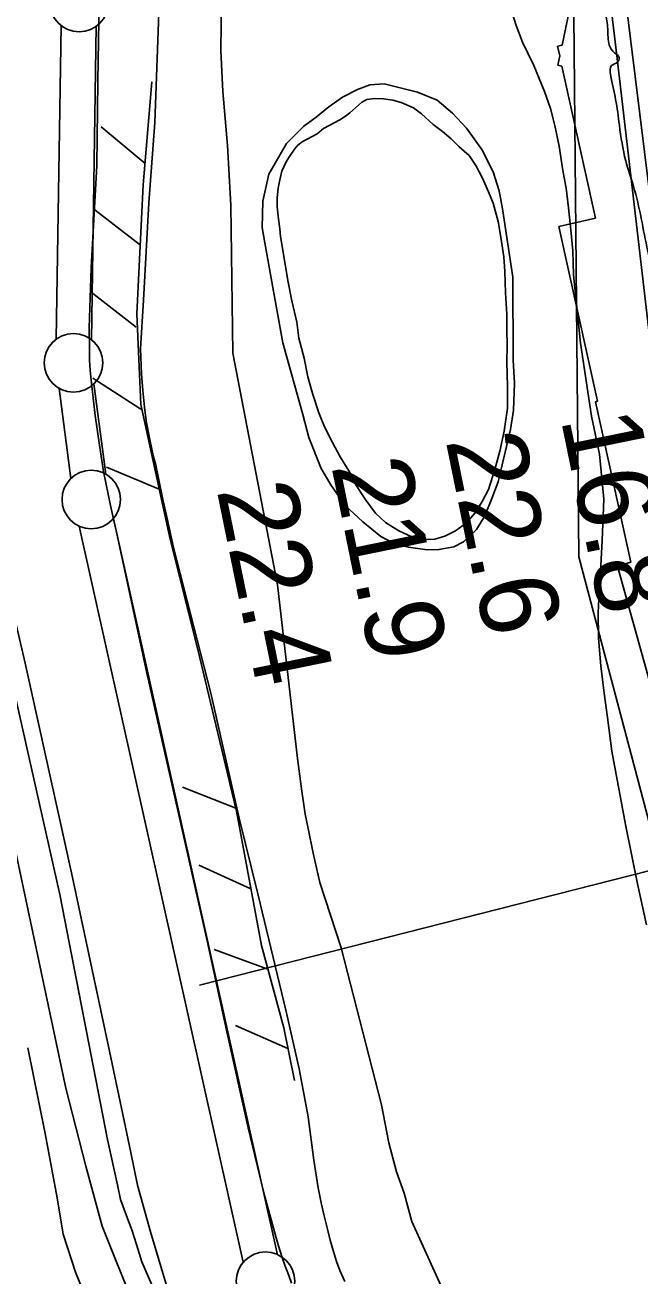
# Model space of a CAD drawing. Extents: x 3424494 to 3462436, y 522220 to 547718.
# Drawn here: x 3438050 to 3438575, y 543668 to 544736 of the extents above; entities that cross this region are included whole.
import ezdxf

# ---------------------------------------------------------------- set-up
doc = ezdxf.new("R2010")
doc.units = 0
for name, color, linetype in [('V-FLOD-BASE', 7, 'Continuous'), ('V-LEVE-TOET', 7, 'Continuous'), ('V-RIVR-EDGE', 7, 'Continuous'), ('V-RIVR-RANG', 7, 'Continuous'), ('V-ROAD-CNTR', 7, 'Continuous'), ('V-RRAP-FSHR', 7, 'Continuous'), ('V-RRAP-RVMT', 7, 'Continuous'), ('V-SITE-VEGE', 7, 'Continuous'), ('V-SURV-LINE', 7, 'Continuous'), ('V-TOPO-DPTH', 7, 'Continuous'), ('V-TOPO-MINR', 7, 'Continuous'), ('V-TOPO-SHOR', 7, 'Continuous')]:
    doc.layers.add(name, color=color, linetype=linetype)

msp = doc.modelspace()

# ---------------------------------------------------------------- linework, layer by layer
at = {"layer": 'V-FLOD-BASE'}
msp.add_lwpolyline([(3438113.5, 544757.3), (3438112.3, 544687.9), (3438111.3, 544616.3), (3438106.5, 544528.9), (3438105, 544477.6), (3438105.1, 544459.8), (3438105.1, 544450.1), (3438105.8, 544441.5), (3438106.4, 544435.6), (3438107.1, 544427.9), (3438109.9, 544402.9), (3438113.6, 544377.6), (3438117.1, 544355.1), (3438123, 544326.1), (3438129.7, 544296.8), (3438153.8, 544184.5), (3438185.2, 544045.4), (3438205.6, 543954.4), (3438222.2, 543878.3), (3438240.8, 543794.9), (3438254.1, 543739.3), (3438264.1, 543702.9), (3438266.6, 543694.3), (3438268.1, 543689.7), (3438270.1, 543683.4), (3438272.4, 543676.9), (3438274, 543672.6), (3438275.5, 543668.8), (3438277.8, 543662.4)], dxfattribs=at)
at = {"layer": 'V-LEVE-TOET'}
for points in [[(3438028.1, 544800.2), (3438027, 544704), (3438012.2, 544549), (3438005.9, 544448), (3438007.1, 544424), (3438010.5, 544382.3), (3438018.3, 544337.7), (3438027, 544290.4), (3438050.2, 544191.5), (3438089.7, 544012.5), (3438122.3, 543860.4), (3438140.5, 543773.8), (3438146.3, 543746), (3438157.2, 543706.2), (3438172.9, 543653.8), (3438191.3, 543608.8), (3438215.1, 543564.4), (3438236.7, 543528.4), (3438271.5, 543473.1)], [(3438164.4, 544746.4), (3438160.9, 544652.8), (3438155.8, 544584.3), (3438151.4, 544501.3), (3438148.6, 544459.7), (3438149.5, 544438), (3438150.7, 544424.2), (3438152, 544409.9), (3438153.6, 544398.2), (3438156.7, 544382.3), (3438159.6, 544368.8), (3438161.8, 544360.4), (3438167.5, 544332.7)], [(3438167.5, 544332.7), (3438171.6, 544314.9), (3438176.8, 544290.1), (3438208.9, 544165.8), (3438233, 544059.1), (3438249, 543994.5), (3438273.2, 543894.3), (3438284.1, 543845.2), (3438291.8, 543804.2), (3438296.8, 543767.3), (3438300.4, 543743.8), (3438302.9, 543730.8), (3438305.3, 543720.8), (3438308.3, 543708.4), (3438310.8, 543698.9), (3438313.5, 543689.3), (3438316.1, 543680.7), (3438319, 543673.1), (3438323.3, 543663.8)]]:
    msp.add_lwpolyline(points, dxfattribs=at)
at = {"layer": 'V-RIVR-EDGE'}
msp.add_spline([(3438393.4, 545837.6), (3438393.6, 545836.9), (3438395.1, 545831.4), (3438401.6, 545826.6), (3438403.8, 545821.1), (3438403.8, 545813.5), (3438405.2, 545801.8), (3438408.5, 545786.4), (3438409.2, 545778), (3438409.2, 545769.9), (3438409.5, 545757.1), (3438410.9, 545744.7), (3438420.3, 545688.8), (3438423.5, 545652.9), (3438428.9, 545606.1), (3438430.6, 545570.3), (3438432.4, 545549.1), (3438435.9, 545504.1), (3438439.2, 545485.5), (3438445, 545463.9), (3438449.3, 545451.8), (3438457.7, 545444.1), (3438458.1, 545439), (3438458.8, 545433.1), (3438463.5, 545430.2), (3438470.8, 545426.9), (3438472.6, 545421.4), (3438472.2, 545413), (3438471.1, 545394.7), (3438468.1, 545380.8), (3438467.8, 545375.4), (3438465.5, 545364.4), (3438464.8, 545351.2), (3438465.9, 545339.9), (3438471.7, 545328.9), (3438480.7, 545301.9), (3438480.7, 545287.2), (3438482.1, 545273.7), (3438487.2, 545258), (3438494.1, 545247), (3438498.9, 545239.3), (3438502.9, 545227.2), (3438508.3, 545196.5), (3438511.1, 545174.2), (3438523.4, 545123), (3438525.6, 545104.7), (3438525.6, 545098.1), (3438527.7, 545082.4), (3438531, 545064.9), (3438530.9, 545051.3), (3438530.5, 545038.9), (3438527.6, 545030.9), (3438526.8, 545021), (3438528.6, 545002.7), (3438527.5, 544975.7), (3438526.3, 544955.6), (3438524.8, 544938.8), (3438527, 544931.8), (3438537.9, 544918.3), (3438543.7, 544908.4), (3438545.5, 544899.2), (3438545.5, 544889.7), (3438542.6, 544875.1), (3438542.2, 544862.7), (3438543.6, 544857.2), (3438543.6, 544855), (3438540.7, 544850.6), (3438539.2, 544841.1), (3438540.3, 544827.2), (3438541.7, 544817.7), (3438545, 544805.3), (3438544.9, 544790.3), (3438543.4, 544767.3), (3438545.9, 544746.4), (3438547.7, 544732.9), (3438549.1, 544719), (3438553.5, 544712.4), (3438557.5, 544708.4), (3438557.1, 544706.2), (3438556, 544704.4), (3438550.9, 544701.5), (3438550.2, 544693.8), (3438554.5, 544672.6), (3438557.7, 544650.6), (3438563.1, 544620.3), (3438569.7, 544598.7), (3438582, 544543.1), (3438585.2, 544523), (3438584.8, 544506.5), (3438588.4, 544491.2), (3438594.9, 544472.5), (3438598.6, 544459), (3438598.5, 544439.6), (3438598.5, 544425), (3438598.1, 544411.8), (3438598.1, 544405.6), (3438599.5, 544397.6), (3438604.2, 544381.1), (3438610.4, 544357), (3438613.3, 544341.6), (3438619.1, 544333.2), (3438624.9, 544321.1), (3438628.1, 544301.7), (3438628.8, 544279.4), (3438635, 544260), (3438635, 544251.3), (3438637.8, 544233.3), (3438638.5, 544216.2), (3438645.1, 544204.1), (3438650.9, 544193.1), (3438650.9, 544182.1), (3438651.6, 544159.1), (3438651.5, 544153.2), (3438653, 544137.5), (3438657.3, 544124), (3438667.1, 544092.9), (3438672.9, 544069.5), (3438679.8, 544048.6), (3438680.5, 544035.5), (3438681.9, 544024.5), (3438680.4, 544017.2), (3438685.5, 544000.7), (3438686.9, 543981.7), (3438692.7, 543957.6), (3438693.8, 543933.1), (3438694.1, 543918.1), (3438698.1, 543900.5), (3438698.4, 543889.9), (3438698.4, 543885.6), (3438701, 543885.2), (3438708.6, 543887.7), (3438712.6, 543882.6), (3438718.5, 543864.7), (3438733.3, 543818.2), (3438741.3, 543793.7), (3438746.7, 543767.4), (3438754, 543734.1), (3438762.3, 543699), (3438771, 543671.5), (3438780, 543642.6), (3438782.9, 543630.9), (3438781.8, 543630.9), (3438771.2, 543630.2), (3438766.9, 543628.8), (3438765.7, 543622.6), (3438771.2, 543615.2), (3438777, 543602.4), (3438775.2, 543590), (3438778.8, 543582.3), (3438781.7, 543581.2), (3438785.7, 543582.3), (3438793.1, 543586.3), (3438797.8, 543584.8), (3438800.4, 543578.2), (3438805.8, 543546.1), (3438811.9, 543525.9), (3438819.5, 543497), (3438822.8, 543490.1), (3438824.6, 543485), (3438830.1, 543471.4), (3438839.9, 543450.9), (3438843.9, 543441.8), (3438850.4, 543423.9), (3438851.9, 543417.3), (3438850.8, 543408.1), (3438850.4, 543400.8), (3438855.1, 543386.2), (3438860.2, 543372.3), (3438866.7, 543366.1), (3438867.8, 543356.5), (3438867.8, 543347.8), (3438868.9, 543341.2), (3438880.5, 543326.9), (3438889.6, 543313), (3438898.7, 543294), (3438902, 543280.1), (3438906, 543265.1), (3438917.2, 543229.6), (3438923, 543209.5), (3438927.7, 543203.6), (3438932.8, 543185.7), (3438937.1, 543160.8), (3438942.6, 543134.8), (3438946.9, 543117.6), (3438946.9, 543110.3), (3438946.5, 543102.7), (3438951.2, 543091.7), (3438960.7, 543082.5), (3438961.4, 543076.7), (3438965.4, 543063.9), (3438966.5, 543053.3), (3438963.9, 543047.4), (3438962.1, 543042.7), (3438965.3, 543026.9), (3438970.4, 543005.4), (3438977.3, 542983.8), (3438982.7, 542973.9), (3438991.8, 542954.9), (3439000.9, 542934), (3439008.6, 542918.6), (3439023.8, 542895.6), (3439028.2, 542883.1), (3439037, 542873.2), (3439040.9, 542860.8), (3439048.2, 542843.6), (3439058.8, 542827.9), (3439070.4, 542802.6), (3439079.5, 542782.8), (3439082.4, 542763.5), (3439082.7, 542749.2), (3439081.6, 542735.3), (3439079.3, 542717.4), (3439079, 542710.5), (3439082.9, 542696.9), (3439086.2, 542687.8), (3439090.6, 542683.8), (3439099.4, 542684.1), (3439102.3, 542680.1), (3439104.1, 542676), (3439104.1, 542668.4), (3439104, 542657.4), (3439105.5, 542647.5), (3439106.2, 542642), (3439115.3, 542621.2), (3439129.1, 542598.9), (3439132.4, 542599.6), (3439141.5, 542584.2), (3439147.3, 542566.6), (3439154.6, 542546.9), (3439164, 542527.5), (3439169.8, 542510.7), (3439173.5, 542500), (3439177.5, 542490.9), (3439190.6, 542472.2), (3439206.2, 542447.3), (3439209.1, 542433.1), (3439211.3, 542426.8), (3439222.3, 542418.4), (3439225.9, 542411.8), (3439227.3, 542401.2), (3439229.9, 542396.1), (3439237.5, 542388), (3439240.4, 542378.9), (3439243, 542371.2), (3439252.8, 542351.1), (3439262.6, 542326.2), (3439271.7, 542310.8), (3439276.4, 542291.8), (3439280.4, 542275.3), (3439282.6, 542264.7), (3439280.4, 542261.1), (3439278.2, 542259.3), (3439283.2, 542243.9), (3439285.4, 542231.8), (3439293.1, 542221.2), (3439297.1, 542211.7), (3439308.3, 542194.5), (3439310.9, 542190.4), (3439316.4, 542190.1), (3439317.5, 542186), (3439322.9, 542161.5), (3439326.9, 542146.2), (3439328.7, 542133.4), (3439327.9, 542118.8), (3439331.1, 542099.7), (3439347.1, 542053.3), (3439351.8, 542035.4), (3439360.5, 542018.9), (3439371.1, 542000.6), (3439381.3, 541982.6), (3439394.1, 541973.1), (3439397.7, 541966.9), (3439399.9, 541955.5), (3439406.1, 541943.5), (3439414.8, 541930.7), (3439422.8, 541920.8), (3439437.8, 541904.6), (3439450.5, 541882.3), (3439460.7, 541852.7), (3439464.7, 541843.9), (3439468.3, 541833.3), (3439481.8, 541815.3), (3439490.1, 541800.7), (3439498.5, 541788.6), (3439505.1, 541778.4), (3439505.4, 541771.4), (3439505.7, 541754.6), (3439506.8, 541747.7), (3439515.2, 541733.7), (3439522.8, 541717.3), (3439531.2, 541708.8), (3439533.8, 541701.2), (3439533.7, 541689.8), (3439534.1, 541670.5), (3439534, 541662), (3439535.5, 541656.6), (3439543.5, 541645.2), (3439555.9, 541625.8), (3439565.7, 541607.5), (3439574, 541583.7), (3439582.8, 541562.5), (3439587.5, 541546.4), (3439591.9, 541542.7), (3439598.8, 541540.2), (3439601.3, 541536.5), (3439607.5, 541524.8), (3439631.5, 541476.8), (3439645.7, 541442.1), (3439652.6, 541429.6), (3439663.2, 541408), (3439674.8, 541397.8), (3439682.8, 541381.3)], degree=3, dxfattribs=at)
at = {"layer": 'V-RIVR-RANG'}
msp.add_line((3438199.1, 543916.7), (3439265.3, 544187.5), dxfattribs=at)
at = {"layer": 'V-ROAD-CNTR'}
msp.add_lwpolyline([(3437857.8, 545838.4), (3437892.6, 545547.7), (3437938.2, 545159.2), (3437964.7, 544952.5), (3437976, 544792.9), (3437969.2, 544630.2), (3437963.9, 544485.3), (3437979.7, 544339.6), (3438022.4, 544122.5), (3438085.1, 543828.8), (3438101.9, 543762.2), (3438116.1, 543710.9), (3438143.5, 543642.1), (3438173.7, 543575.3), (3438251, 543447.6), (3438348.6, 543287), (3438420.9, 543170.8), (3438482.6, 543068.5), (3438531.5, 542958.1)], dxfattribs=at)
at = {"layer": 'V-RRAP-FSHR'}
for p, q in [((3438152.6, 544618), (3438115.1, 544649.2)), ((3438148.6, 544548.1), (3438110, 544578)), ((3438145.1, 544478.2), (3438106.5, 544508.1)), ((3438149.1, 544408.2), (3438107.9, 544434.6)), ((3438164.7, 544339.9), (3438119.7, 544358.7)), ((3438230, 544067.7), (3438184.6, 544085.6)), ((3438243, 543998.9), (3438198.5, 544019.1)), ((3438257.4, 543930.4), (3438211.5, 543947)), ((3438274.6, 543862.6), (3438229.8, 543882.1))]:
    msp.add_line(p, q, dxfattribs=at)
for points in [[(3438158.5, 544687.7), (3438151.1, 544599.8), (3438145.7, 544489.6), (3438148.9, 544412.2), (3438173.5, 544299.9), (3438199, 544197.2), (3438230.6, 544065.1), (3438252, 543950.6), (3438271, 543880.3), (3438280.1, 543835.2)], [(3438158.5, 544687.7), (3438151.1, 544599.8), (3438145.7, 544489.6), (3438148.9, 544412.2), (3438163.7, 544344.8)], [(3438225, 544088.7), (3438230.6, 544065.1), (3438252, 543950.6), (3438271, 543880.3), (3438280.1, 543835.2)]]:
    msp.add_lwpolyline(points, dxfattribs=at)
at = {"layer": 'V-RRAP-RVMT'}
for p, q in [((3438508.7, 544719), (3438515.5, 544750.5)), ((3438504.9, 544718.1), (3438508.7, 544719)), ((3438506.7, 544709.7), (3438504.9, 544718.1)), ((3438505, 544701.8), (3438506.7, 544709.7)), ((3438508.6, 544701), (3438505, 544701.8)), ((3438537.3, 544571.2), (3438508.6, 544701)), ((3438506.1, 544564.3), (3438537.3, 544571.2)), ((3438539.1, 544415), (3438506.1, 544564.3)), ((3438537.2, 544414.6), (3438539.1, 544415)), ((3438567.5, 544277.6), (3438537.2, 544414.6)), ((3438556, 544274.4), (3438567.5, 544277.6)), ((3438600.2, 544115.1), (3438556, 544274.4))]:
    msp.add_line(p, q, dxfattribs=at)
at = {"layer": 'V-SITE-VEGE'}
for points in [[(3438412.3, 543644.6), (3438380.3, 543714.9), (3438373.9, 543739), (3438367.3, 543757.3), (3438360.7, 543782), (3438354.5, 543814.4), (3438320.2, 543948.4), (3438302, 544004.4), (3438296.3, 544029.2), (3438291.8, 544050.5), (3438289.3, 544062.5), (3438286.1, 544084.2), (3438282.8, 544110), (3438265.6, 544258.4), (3438227.6, 544456.2), (3438225.9, 544582.4), (3438223.1, 544633.3), (3438219.1, 544679.5), (3438217.4, 544714.4), (3438218, 544759.9)], [(3438465.7, 544747.4), (3438469.4, 544735.7), (3438474.9, 544721.6), (3438484.6, 544701.7), (3438493.8, 544679.5), (3438499, 544665), (3438502.7, 544650.4), (3438506.4, 544632.8), (3438509.5, 544611.9), (3438512.2, 544597), (3438514.1, 544580.1), (3438516.3, 544561.2), (3438517.8, 544543.4), (3438518.5, 544522.8), (3438524.6, 544464.5), (3438533.8, 544402.4), (3438540.8, 544369.9), (3438544.5, 544331.5), (3438542.9, 544296.2), (3438541.9, 544274.9), (3438540.3, 544251.9), (3438539.6, 544234.8), (3438539.9, 544212.9), (3438541.8, 544189.1), (3438544.8, 544165.9), (3438547.4, 544145.2), (3438551.2, 544116.3), (3438562.8, 544053.7), (3438573.2, 544003.1), (3438580.9, 543968.1)]]:
    msp.add_lwpolyline(points, dxfattribs=at)
msp.add_lwpolyline([(3438273.5, 544635), (3438258.2, 544608.8), (3438253.2, 544585.7), (3438252.6, 544563.3), (3438254.8, 544550.3), (3438264.3, 544498), (3438270.4, 544464.9), (3438287.4, 544403.7), (3438292.6, 544384.2), (3438303.1, 544357.7), (3438311.3, 544343.7), (3438323.6, 544326.1), (3438338.5, 544312.1), (3438353.9, 544299.5), (3438364.8, 544293.9), (3438377.7, 544290.4), (3438393.5, 544288.3), (3438403.5, 544288.4), (3438416.2, 544290.9), (3438424.6, 544295.1), (3438435.7, 544305.6), (3438442.8, 544317.2), (3438448.9, 544331.9), (3438454.1, 544346.2), (3438464.7, 544391), (3438467.2, 544407.3), (3438468, 544430.5), (3438467.1, 544450.2), (3438466.8, 544520.9), (3438457.9, 544579.2), (3438454.9, 544594.5), (3438450, 544610.7), (3438440.3, 544630), (3438427.2, 544648.1), (3438415.2, 544660.9), (3438402.2, 544672.1), (3438385.2, 544678.9), (3438356.9, 544685.8), (3438344.7, 544685), (3438334, 544681.1), (3438321.1, 544674.5), (3438309.7, 544666.3), (3438298.7, 544657.6), (3438291.4, 544652.1), (3438288.1, 544649.9)], close=True, dxfattribs=at)
at = {"layer": 'V-SURV-LINE'}
for points in [[(3438076.8, 544468), (3438081, 544735.6)], [(3438076.8, 544468), (3438081, 544735.6)], [(3438110.9, 544735.1), (3438106.8, 544467.5)], [(3438110.9, 544735.1), (3438106.8, 544467.5)], [(3438089.3, 544349), (3438079.2, 544426)], [(3438089.3, 544349), (3438079.2, 544426)], [(3438108.9, 544429.9), (3438119, 544352.9)], [(3438108.9, 544429.9), (3438119, 544352.9)], [(3438236.4, 543680.1), (3438096.4, 544308.4)], [(3438236.4, 543680.1), (3438096.4, 544308.4)], [(3438125.7, 544314.9), (3438265.7, 543686.6)], [(3438125.7, 544314.9), (3438265.7, 543686.6)]]:
    msp.add_lwpolyline(points, dxfattribs=at)
for centre in [(3438096.3, 544755.3), (3438091.5, 544447.8), (3438106.7, 544331.2), (3438255.4, 543663.9)]:
    msp.add_circle(centre, 25, dxfattribs=at)
at = {"layer": 'V-TOPO-DPTH'}
msp.add_lwpolyline([(3438555.3, 544821), (3438567.2, 544724.4), (3438579.1, 544627.9), (3438591.1, 544531.4), (3438614.4, 544345), (3438617.3, 544323.7), (3438620.6, 544302.3), (3438624.5, 544281.1), (3438628.8, 544260), (3438729.5, 543790.7), (3438747.1, 543713.4), (3438766, 543636.4), (3438786.8, 543559.8), (3438808.9, 543483.7), (3438839.5, 543382.7), (3438847.5, 543357.3), (3438855.8, 543332.1), (3438864.5, 543306.9), (3438873.6, 543281.9), (3438986.9, 542979.3)], dxfattribs=at)
at = {"layer": 'V-TOPO-MINR'}
for points in [[(3438517.3, 544899.2), (3438523, 544282.1), (3438689.4, 543654.9), (3438784.3, 543333), (3438787.3, 543323.2), (3438790.4, 543313.3), (3439064.6, 542639.3)], [(3438555.3, 544821), (3438567.2, 544724.4), (3438579.1, 544627.9), (3438591.1, 544531.4), (3438614.4, 544345), (3438617.3, 544323.7), (3438620.6, 544302.3), (3438624.5, 544281.1), (3438628.8, 544260), (3438729.5, 543790.7), (3438747.1, 543713.4), (3438766, 543636.4), (3438786.8, 543559.8), (3438808.9, 543483.7), (3438839.5, 543382.7), (3438847.5, 543357.3), (3438855.8, 543332.1), (3438864.5, 543306.9), (3438873.6, 543281.9), (3438986.9, 542979.3)], [(3438547.9, 544774.4), (3438555.7, 544707.5), (3438596.4, 544358.3), (3438600.3, 544328.6), (3438604.7, 544299), (3438610, 544269.6), (3438615.9, 544240.2), (3438795.9, 543401.4), (3438799, 543387.9), (3438802.4, 543374.5), (3438806.3, 543361.1), (3438810.4, 543347.9), (3438814.8, 543334.7), (3438819.5, 543321.7), (3439067.8, 542705.5)]]:
    msp.add_lwpolyline(points, dxfattribs=at)
at = {"layer": 'V-TOPO-SHOR'}
for points in [[(3438299.6, 544643.3), (3438305, 544647.9), (3438318.9, 544655.1), (3438323.8, 544658.3), (3438327.6, 544661.2), (3438332.4, 544665.5), (3438337.6, 544670.2), (3438341.9, 544672.5), (3438348.9, 544673.4), (3438356.3, 544673.1), (3438364.1, 544672), (3438371.4, 544669.9), (3438381.9, 544665.5), (3438388.7, 544660.2), (3438398.8, 544651.2), (3438406.5, 544645.3), (3438413.9, 544639), (3438421, 544632.3), (3438429.3, 544624.7), (3438435, 544616.2), (3438440.8, 544605.4), (3438445.9, 544593.7), (3438449.8, 544584), (3438454.2, 544568.4), (3438456.5, 544555.1), (3438459, 544538.3), (3438459.8, 544525.7), (3438460.5, 544507.5), (3438461.6, 544489.3), (3438461.7, 544475.7), (3438461.8, 544463), (3438461.6, 544448), (3438462.2, 544427.8), (3438462.2, 544409), (3438459.2, 544389.6), (3438455.5, 544372.5), (3438451.4, 544356.7), (3438445.8, 544339.7), (3438440.6, 544329.4), (3438434.4, 544319.7), (3438427, 544311.3), (3438417.6, 544304.5), (3438408.5, 544299.9), (3438400.2, 544297.3), (3438390.1, 544297.1), (3438380.3, 544299.3), (3438369.3, 544304.4), (3438358, 544311.5), (3438349.3, 544319.6), (3438340.5, 544331.5), (3438333.1, 544342.7), (3438326.5, 544355.7), (3438319.2, 544367.6), (3438312.7, 544379.8), (3438305.9, 544393.1), (3438301, 544405.1), (3438295.9, 544420.8), (3438291.6, 544435.8), (3438288.4, 544451.8), (3438284, 544468.8), (3438282.2, 544482.6), (3438278, 544500.6), (3438274.7, 544516.6), (3438268.2, 544555.5), (3438267.7, 544562.2), (3438266.6, 544570.5), (3438265.4, 544581), (3438265.5, 544588.7), (3438266.4, 544596.9), (3438267.6, 544604), (3438269.4, 544611.5), (3438273.2, 544619.4), (3438276, 544623.9), (3438280.3, 544630.2), (3438283.2, 544633.6), (3438286.9, 544636.5), (3438299.6, 544643.3)], [(3438021.5, 544252.4), (3438079.9, 543994), (3438110.5, 543836), (3438120.5, 543784.8), (3438126.1, 543759), (3438129.1, 543746.1), (3438131.6, 543733.7), (3438136.7, 543719.7), (3438141.3, 543707.8), (3438145.3, 543695.4), (3438149.9, 543680.4), (3438156.5, 543665.4), (3438164.1, 543648.3), (3438171.3, 543631.3), (3438176.9, 543617.8), (3438182.5, 543604.4), (3438191.7, 543587.3), (3438233.1, 543521), (3438292.9, 543423.1), (3438455.5, 543160.6)], [(3438124.4, 543595), (3438093.3, 543671.6), (3438082.7, 543704.1), (3438077.7, 543735.1), (3438067.2, 543789.9), (3438052.6, 543863.2)]]:
    msp.add_lwpolyline(points, dxfattribs=at)

# ---------------------------------------------------------------- texts
at = {"layer": 'V-RIVR-RANG'}
for s, p in [('16.8', (3438507.5, 544400.3)), ('22.6', (3438409.2, 544381.8)), ('21.9', (3438311.6, 544360)), ('22.4', (3438213.7, 544339.5))]:
    msp.add_text(s, height=67, rotation=281.5383, dxfattribs=at).set_placement(p)

doc.saveas('drawing.dxf')
